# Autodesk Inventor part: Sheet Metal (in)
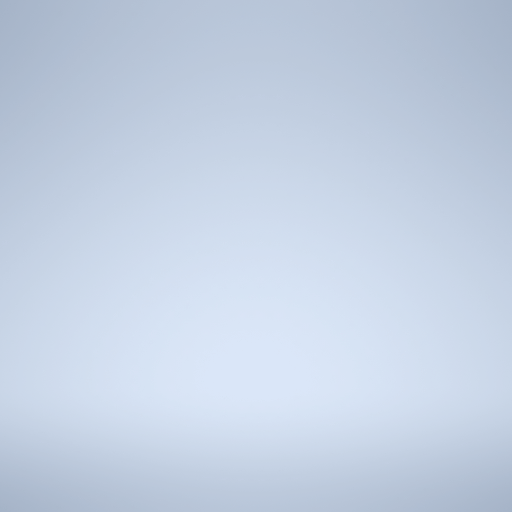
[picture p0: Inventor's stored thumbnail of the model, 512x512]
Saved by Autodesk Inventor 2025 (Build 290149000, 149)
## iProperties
Created: 2024-02
Part Number: Sheet Metal (in)
Material: Generico
Document SubType Name: Sheet Metal
Density: 1 g/cm^3
Sheet Metal Rule: Default
Appearance: Default
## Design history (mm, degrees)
other parameters: "Spessore" = 3.048, "RaggioPiega" = 3.048 (= Spessore), "LarghezzaScaricoPiega" = 3.048 (= Spessore), "ProfonditàScaricoPiega" = 1.524 (= 0.5 x Spessore), "DimensioniScaricoAngolo" = 12.192 (= 4 x Spessore), "SeamGap" = 0.00508, "ResiduoMinimo" = 6.096 (= 2 x Spessore), "RaggioTransizione" = 3.048 (= RaggioPiega), "Dimensione_raggio_Jacobi" = 3.048 (= RaggioPiega), "DimensioneGioco" = 3.048 (= Spessore)
